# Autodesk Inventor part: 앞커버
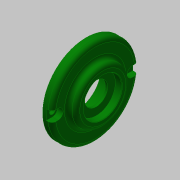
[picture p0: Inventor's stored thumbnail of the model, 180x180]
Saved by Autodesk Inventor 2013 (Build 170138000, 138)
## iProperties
Created: 2019-06
Part Number: 앞커버
Material: 알루미늄 6061
Document SubType Name: Modeling
Designer: mduedu
Density: 2.71 g/cm^3
Mass: 82.9835 g
Surface Area: 113.272 cm^2
Volume: 30.6212 cm^3
Author: mduedu
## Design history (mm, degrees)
sketch "스케치1"
  geometry: L1 (0, 0)-(7, 0); L2 (7, 0)-(7, 25); L3 (7, 25)-(0, 25); L4 (0, 25)-(0, 0); L5 (7, 0)-(14, 0); L6 (14, 0)-(14, 34); L7 (14, 34)-(7, 34); L8 (7, 34)-(7, 0); L9 (14, 0)-(20, 0); L10 (20, 0)-(20, 21); L11 (20, 21)-(14, 21); L12 (14, 21)-(14, 0)
  constraints: 24 end point, 6 parallel, 3 horizontal, 3 perpendicular
  dimensions: "d0" = 20 distance between parallel lines of L10 L4; "d2" = 7 distance of L2.end L3.end; "d3" = 7 distance of L6.end L7.end; "d4" = 50 diameter of L3 L1; "d5" = 68 diameter of L7 L5; "d6" = 42 diameter of L11 L9
revolve "회전1" sketch "스케치1" stored, may be unused: angle "d7" = 90 deg
sketch "스케치2"
  geometry: L1 (0, -25)-(0, 25) reference; L2 (0, 25)-(7, 25) reference; L3 (7, 25)-(7, 34) reference; L4 (7, 34)-(14, 34) reference; L5 (14, 34)-(14, 21) reference; L6 (14, 21)-(20, 21) reference; L7 (20, 21)-(20, -21) reference; L8 (20, -21)-(14, -21) reference; L9 (14, -21)-(14, -34) reference; L10 (14, -34)-(7, -34) reference; L11 (7, -34)-(7, -25) reference; L12 (7, -25)-(0, -25) reference; L13 (10, 0)-(10, 17.5); L14 (10, 17.5)-(0, 17.5); L15 (0, 17.5)-(0, 0); L16 (13, 0)-(13, 15); L17 (13, 15)-(10, 15); L18 (10, 15)-(10, 0); L19 (14.8, 0)-(14.8, 9); L20 (14.8, 9)-(13, 9); L21 (13, 9)-(13, 0); L22 (20, 0)-(20, 15); L23 (20, 15)-(14.8, 15); L24 (14.8, 15)-(14.8, 0)
  constraints: 24 end point, 4 horizontal, 4 horizontal alignment, 4 parallel, 4 vertical, 1 point on line, 8 other
  dimensions: "d8" = 35 dimension on L14; "d10" = 30 dimension on L17; "d11" = 18 dimension on L20; "d12" = 30 dimension on L23; "d13" = 10 distance of L13.end L14.end; "d14" = 3 distance of L16.end L17.end; "d15" = 5.2 distance of L22.end L23.end
revolve "회전2" sketch "스케치2" stored, may be unused: angle "d16" = 90 deg
chamfer "모따기1" distance "d18" = 0.5; stored, may be unused: second distance "d19" = 2, angle "d20" = 30 deg
fillet "모깎기2" dims "d21" = 0.3
fillet "모깎기3" dims "d22" = 3
chamfer "모따기2" distance "d23" = 1; stored, may be unused: second distance "d24" = 2, angle "d25" = 30 deg
fillet "모깎기4" dims "d26" = 3
sketch "스케치3" dims "d27" = 58
  geometry: L1 (-4, 29)-(-4, 33.764); L2 (4, 33.764)-(4, 29); A1 r 4 centre (0, 29) between (-4, 29) and (4, 29); A2 r 34 centre (0, 0) between (4, 33.764) and (-4, 33.764); A3 r 34 centre (0, 0) between (4, 33.764) and (-4, 33.764) reference; 3 further points
  constraints: 6 point on circle, 4 end point, 3 coincident, 2 centre point, 2 tangent, 2 vertical, 2 vertical alignment, 1 concentric, 2 other
  dimensions: "d28" = 8 diameter of A1
extrude "돌출1" cut sketch "스케치3" distance "d29" = 4.4; taper "d30" = 0 deg
sketch "스케치4"
  geometry: A1 r 4 centre (0, 29) between (-4, 29) and (4, 29) reference; 2 further points
  constraints: 1 coincident
hole "구멍1" sketch "스케치4" at (0, 29) diameter "d34" = 4.5; stored, may be unused: countersink angle "d38" = 90 deg, drill point angle "d40" = 118 deg; dims "d35" = 6, "d36" = 4, "d37" = 2, "d39" = 8
node "솔리드1"
pattern_circular "원형 패턴1" dims angle "d32" = 360 deg
pattern_circular "원형 패턴2" dims angle "d42" = 360 deg
node "절단 모서리 투영1"
